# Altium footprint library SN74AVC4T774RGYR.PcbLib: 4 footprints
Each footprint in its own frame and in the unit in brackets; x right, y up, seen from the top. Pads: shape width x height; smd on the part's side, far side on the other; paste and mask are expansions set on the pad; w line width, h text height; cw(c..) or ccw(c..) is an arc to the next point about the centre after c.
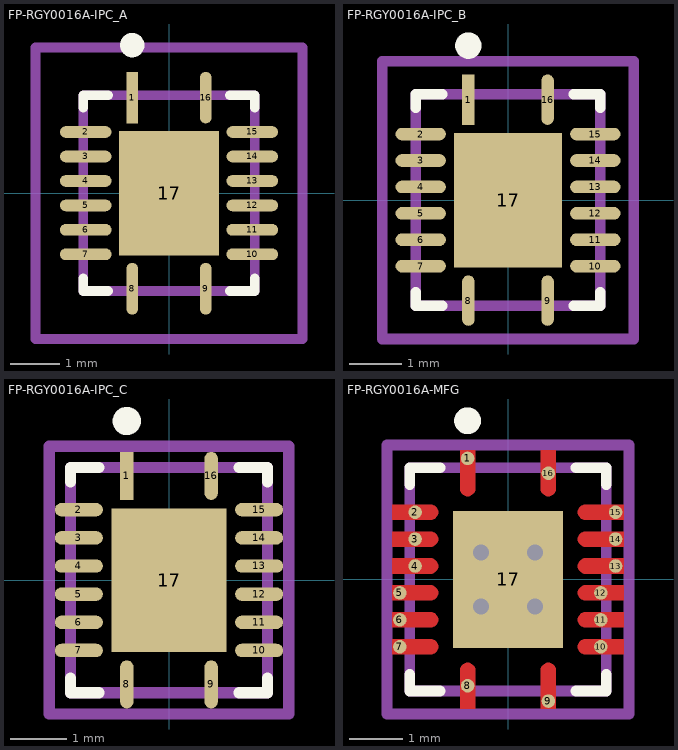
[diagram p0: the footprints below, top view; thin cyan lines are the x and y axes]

## FP-RGY0016A-IPC_A [mm]
pads (17):
  rect 0.239x1.054 smd paste+0 mask+0: 1(-0.75,1.952)
  rrect100% 1.054x0.239 smd paste+0 mask+0: 2(-1.702,1.25) 3(-1.702,0.75) 4(-1.702,0.25) 5(-1.702,-0.25) 6(-1.702,-0.75) 7(-1.702,-1.25) 10(1.702,-1.25) 11(1.702,-0.75) 12(1.702,-0.25) 13(1.702,0.25) 14(1.702,0.75) 15(1.702,1.25)
  rrect100% 0.239x1.054 smd paste+0 mask+0: 8(-0.75,-1.952) 9(0.75,-1.952) 16(0.75,1.952)
  rect 2.05x2.55 smd paste-1000 mask+0: 17(0,0)
Top Overlay:
  circle w0.25: c-0.75,3.025 r0.125
  lines w0.2: -1.75,-1.745 -1.75,-2 -1.245,-2 ; -1.75,1.745 -1.75,2 -1.245,2 ; 1.245,-2 1.75,-2 1.75,-1.745 ; 1.245,2 1.75,2 1.75,1.745
Top Paste:
  rectangle: -0.609,-0.859 0.609,0.859
Mechanical 5:
  lines w0.2: -2.729,-2.979 2.729,-2.979 2.729,2.979 -2.729,2.979 -2.729,-2.979
  text ".Designator" at 0,0.188 h1
Mechanical 13:
  lines w0.2: -1.75,-2 1.75,-2 1.75,2 -1.75,2 -1.75,-2
Mechanical 15:
  lines w0.2: -2.729,-2.979 2.729,-2.979 2.729,2.979 -2.729,2.979 -2.729,-2.979
Mechanical 16:
  lines w0.1: -0.5,0 0.5,0 ; 0,-0.5 0,0.5
3D body "IC_Texas_Instruments_SN74AVC4T774RGYR_eec.STEP": height 0.25, standoff 0, extent -2.729,-2.979 2.729,2.979

## FP-RGY0016A-IPC_B [mm]
pads (17):
  rect 0.239x0.954 smd paste+0 mask+0: 1(-0.75,1.902)
  rrect100% 0.954x0.239 smd paste+0 mask+0: 2(-1.652,1.25) 3(-1.652,0.75) 4(-1.652,0.25) 5(-1.652,-0.25) 6(-1.652,-0.75) 7(-1.652,-1.25) 10(1.652,-1.25) 11(1.652,-0.75) 12(1.652,-0.25) 13(1.652,0.25) 14(1.652,0.75) 15(1.652,1.25)
  rrect100% 0.239x0.954 smd paste+0 mask+0: 8(-0.75,-1.902) 9(0.75,-1.902) 16(0.75,1.902)
  rect 2.05x2.55 smd paste-1000 mask+0: 17(0,0)
Top Overlay:
  circle w0.25: c-0.75,2.925 r0.125
  lines w0.2: -1.75,-1.745 -1.75,-2 -1.245,-2 ; -1.75,1.745 -1.75,2 -1.245,2 ; 1.245,-2 1.75,-2 1.75,-1.745 ; 1.245,2 1.75,2 1.75,1.745
Top Paste:
  rectangle: -0.609,-0.859 0.609,0.859
Mechanical 5:
  lines w0.2: -2.379,-2.629 2.379,-2.629 2.379,2.629 -2.379,2.629 -2.379,-2.629
  text ".Designator" at 0,0.188 h1
Mechanical 13:
  lines w0.2: -1.75,-2 1.75,-2 1.75,2 -1.75,2 -1.75,-2
Mechanical 15:
  lines w0.2: -2.379,-2.629 2.379,-2.629 2.379,2.629 -2.379,2.629 -2.379,-2.629
Mechanical 16:
  lines w0.1: -0.5,0 0.5,0 ; 0,-0.5 0,0.5
3D body "IC_Texas_Instruments_SN74AVC4T774RGYR_eec.STEP": height 0.25, standoff 0, extent -2.379,-2.629 2.379,2.629

## FP-RGY0016A-IPC_C [mm]
pads (17):
  rect 0.239x0.854 smd paste+0 mask+0: 1(-0.75,1.852)
  rrect100% 0.854x0.239 smd paste+0 mask+0: 2(-1.602,1.25) 3(-1.602,0.75) 4(-1.602,0.25) 5(-1.602,-0.25) 6(-1.602,-0.75) 7(-1.602,-1.25) 10(1.602,-1.25) 11(1.602,-0.75) 12(1.602,-0.25) 13(1.602,0.25) 14(1.602,0.75) 15(1.602,1.25)
  rrect100% 0.239x0.854 smd paste+0 mask+0: 8(-0.75,-1.852) 9(0.75,-1.852) 16(0.75,1.852)
  rect 2.05x2.55 smd paste-1000 mask+0: 17(0,0)
Top Overlay:
  circle w0.25: c-0.75,2.825 r0.125
  lines w0.2: -1.75,-1.745 -1.75,-2 -1.245,-2 ; -1.75,1.745 -1.75,2 -1.245,2 ; 1.245,-2 1.75,-2 1.75,-1.745 ; 1.245,2 1.75,2 1.75,1.745
Top Paste:
  rectangle: -0.609,-0.859 0.609,0.859
Mechanical 5:
  lines w0.2: -2.129,-2.379 2.129,-2.379 2.129,2.379 -2.129,2.379 -2.129,-2.379
  text ".Designator" at 0,0.188 h1
Mechanical 13:
  lines w0.2: -1.75,-2 1.75,-2 1.75,2 -1.75,2 -1.75,-2
Mechanical 15:
  lines w0.2: -2.129,-2.379 2.129,-2.379 2.129,2.379 -2.129,2.379 -2.129,-2.379
Mechanical 16:
  lines w0.1: -0.5,0 0.5,0 ; 0,-0.5 0,0.5
3D body "IC_Texas_Instruments_SN74AVC4T774RGYR_eec.STEP": height 0.25, standoff 0, extent -2.129,-2.379 2.129,2.379

## FP-RGY0016A-MFG [mm]
pads (17):
  round 0.252 smd paste-1000 mask+0: 1(-0.75,2.25) 2(-1.725,1.25) 3(-1.725,0.75) 4(-1.725,0.25) 5(-2.01,-0.25) 6(-2.01,-0.75) 7(-2.01,-1.25) 8(-0.75,-1.975) 9(0.75,-2.26) 10(1.725,-1.25) 11(1.725,-0.75) 12(1.725,-0.25) 13(2,0.25) 14(2,0.75) 15(2,1.25) 16(0.75,1.975)
  rect 2.05x2.55 smd paste-1000 mask+0: 17(0,0)
via 0.5,0.5 diameter 0.6 hole 0.3
via 0.5,-0.5 diameter 0.6 hole 0.3
via -0.5,0.5 diameter 0.6 hole 0.3
via -0.5,-0.5 diameter 0.6 hole 0.3
Top Layer:
  region: -0.61,2.4 -0.61,1.69 -0.61,1.662 -0.631,1.611 -0.671,1.571 -0.722,1.55 -0.75,1.55 -0.778,1.55 -0.829,1.571 -0.869,1.611 -0.89,1.662 -0.89,1.69 -0.89,2.4
  region: -2.15,1.39 -1.44,1.39 -1.412,1.39 -1.361,1.369 -1.321,1.329 -1.3,1.278 -1.3,1.25 -1.3,1.222 -1.321,1.171 -1.361,1.131 -1.412,1.11 -1.44,1.11 -2.15,1.11
  region: -2.15,0.89 -1.44,0.89 -1.412,0.89 -1.361,0.869 -1.321,0.829 -1.3,0.778 -1.3,0.75 -1.3,0.722 -1.321,0.671 -1.361,0.631 -1.412,0.61 -1.44,0.61 -2.15,0.61
  region: -2.15,0.39 -1.44,0.39 -1.412,0.39 -1.361,0.369 -1.321,0.329 -1.3,0.278 -1.3,0.25 -1.3,0.222 -1.321,0.171 -1.361,0.131 -1.412,0.11 -1.44,0.11 -2.15,0.11
  region: -2.15,-0.11 -1.44,-0.11 -1.412,-0.11 -1.361,-0.131 -1.321,-0.171 -1.3,-0.222 -1.3,-0.25 -1.3,-0.278 -1.321,-0.329 -1.361,-0.369 -1.412,-0.39 -1.44,-0.39 -2.15,-0.39
  region: -2.15,-0.61 -1.44,-0.61 -1.412,-0.61 -1.361,-0.631 -1.321,-0.671 -1.3,-0.722 -1.3,-0.75 -1.3,-0.778 -1.321,-0.829 -1.361,-0.869 -1.412,-0.89 -1.44,-0.89 -2.15,-0.89
  region: -2.15,-1.11 -1.44,-1.11 -1.412,-1.11 -1.361,-1.131 -1.321,-1.171 -1.3,-1.222 -1.3,-1.25 -1.3,-1.278 -1.321,-1.329 -1.361,-1.369 -1.412,-1.39 -1.44,-1.39 -2.15,-1.39
  region: 2.15,-1.39 1.44,-1.39 1.412,-1.39 1.361,-1.369 1.321,-1.329 1.3,-1.278 1.3,-1.25 1.3,-1.222 1.321,-1.171 1.361,-1.131 1.412,-1.11 1.44,-1.11 2.15,-1.11
  region: 2.15,-0.89 1.44,-0.89 1.412,-0.89 1.361,-0.869 1.321,-0.829 1.3,-0.778 1.3,-0.75 1.3,-0.722 1.321,-0.671 1.361,-0.631 1.412,-0.61 1.44,-0.61 2.15,-0.61
  region: 2.15,-0.39 1.44,-0.39 1.412,-0.39 1.361,-0.369 1.321,-0.329 1.3,-0.278 1.3,-0.25 1.3,-0.222 1.321,-0.171 1.361,-0.131 1.412,-0.11 1.44,-0.11 2.15,-0.11
  region: 2.15,0.11 1.44,0.11 1.412,0.11 1.361,0.131 1.321,0.171 1.3,0.222 1.3,0.25 1.3,0.278 1.321,0.329 1.361,0.369 1.412,0.39 1.44,0.39 2.15,0.39
  region: 2.15,0.61 1.44,0.61 1.412,0.61 1.361,0.631 1.321,0.671 1.3,0.722 1.3,0.75 1.3,0.778 1.321,0.829 1.361,0.869 1.412,0.89 1.44,0.89 2.15,0.89
  region: 2.15,1.11 1.44,1.11 1.412,1.11 1.361,1.131 1.321,1.171 1.3,1.222 1.3,1.25 1.3,1.278 1.321,1.329 1.361,1.369 1.412,1.39 1.44,1.39 2.15,1.39
  region: -0.89,-2.4 -0.89,-1.69 -0.89,-1.662 -0.869,-1.611 -0.829,-1.571 -0.778,-1.55 -0.75,-1.55 -0.722,-1.55 -0.671,-1.571 -0.631,-1.611 -0.61,-1.662 -0.61,-1.69 -0.61,-2.4
  region: 0.61,-2.4 0.61,-1.69 0.61,-1.662 0.631,-1.611 0.671,-1.571 0.722,-1.55 0.75,-1.55 0.778,-1.55 0.829,-1.571 0.869,-1.611 0.89,-1.662 0.89,-1.69 0.89,-2.4
  region: 0.89,2.4 0.89,1.69 0.89,1.662 0.869,1.611 0.829,1.571 0.778,1.55 0.75,1.55 0.722,1.55 0.671,1.571 0.631,1.611 0.61,1.662 0.61,1.69 0.61,2.4
Top Overlay:
  circle w0.25: c-0.75,2.95 r0.125
  lines w0.2: -1.825,-1.765 -1.825,-2.075 -1.265,-2.075 ; -1.825,1.765 -1.825,2.075 -1.265,2.075 ; 1.265,-2.075 1.825,-2.075 1.825,-1.765 ; 1.265,2.075 1.825,2.075 1.825,1.765
Top Paste:
  drawing of 20 lines, arcs and shapes, not listed
Mechanical 5:
  lines w0.2: -2.25,-2.5 2.25,-2.5 2.25,2.5 -2.25,2.5 -2.25,-2.5
  text ".Designator" at 0,-0.001 h1
Mechanical 13:
  lines w0.2: -1.825,-2.075 1.825,-2.075 1.825,2.075 -1.825,2.075 -1.825,-2.075
Mechanical 15:
  lines w0.2: -2.25,-2.5 2.25,-2.5 2.25,2.5 -2.25,2.5 -2.25,-2.5
Mechanical 16:
  lines w0.1: -0.675,0 0.675,0 ; 0,-0.675 0,0.675
3D body "IC_Texas_Instruments_SN74AVC4T774RGYR_eec.STEP": height 0.25, standoff 0, extent -2.25,-2.5 2.25,2.5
